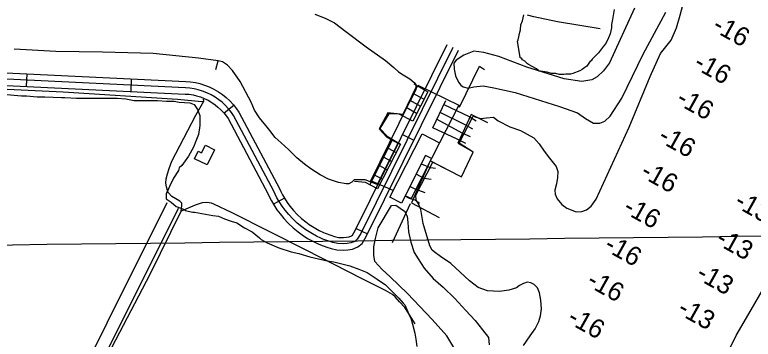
# Model space of a CAD drawing. Extents: x 3683402 to 3721514, y 487807 to 513565.
# Drawn here: x 3701138 to 3702904, y 505272 to 506048 of the extents above; entities that cross this region are included whole.
import ezdxf

# ---------------------------------------------------------------- set-up
doc = ezdxf.new("R2010")
doc.units = 0
for name, color, linetype in [('V-BLDG-OTLN', 7, 'Continuous'), ('V-GRID-MAJR', 7, 'Continuous'), ('V-LEVE-TOET', 7, 'Continuous'), ('V-ROAD-CNTR', 7, 'Continuous'), ('V-RRAP-FSHR', 7, 'Continuous'), ('V-RTRN-LOCK-CHMB', 7, 'Continuous'), ('V-SITE-VEGE', 7, 'Continuous'), ('V-TOPO-SHOR', 7, 'Continuous'), ('V-TOPO-SPOT', 7, 'Continuous'), ('V-UTIL-LINE', 7, 'Continuous')]:
    doc.layers.add(name, color=color, linetype=linetype)

msp = doc.modelspace()

# ---------------------------------------------------------------- linework, layer by layer
at = {"layer": 'V-BLDG-OTLN'}
for points in [[(3702034.7, 505611.3), (3702111.8, 505763), (3702153.7, 505741.7), (3702134.3, 505703.6), (3702120, 505710.9), (3702062.3, 505597.3)], [(3701615.6, 505724.6), (3701598.1, 505688.5), (3701567.7, 505703.3), (3701576.5, 505721.5), (3701584.6, 505717.5), (3701593.4, 505735.5)]]:
    msp.add_lwpolyline(points, close=True, dxfattribs=at)
at = {"layer": 'V-GRID-MAJR'}
msp.add_spline([(3687515.9, 505342.9), (3692797.3, 505402.5), (3698078.7, 505462.8), (3703360, 505523.8), (3708641.3, 505585.7), (3713922.7, 505648.3), (3719204, 505711.6)], degree=3, dxfattribs=at)
at = {"layer": 'V-LEVE-TOET'}
for points in [[(3702619.9, 506063.6), (3702559.8, 505932.3), (3702545.4, 505913.3), (3702530.1, 505899.4), (3702517.7, 505892.4), (3702493.9, 505888.3), (3702451.6, 505894.6), (3702362.1, 505922.6), (3702295, 505948.2), (3702259.7, 505957.5), (3702235.8, 505960.9), (3702211.5, 505950.9), (3702193.2, 505938.9), (3702187.7, 505931.5), (3702188.8, 505917.6), (3702191.3, 505901.7), (3702198.8, 505886.3), (3702204.3, 505879.4), (3702209.8, 505875.4), (3702221.7, 505872.5), (3702235.1, 505875), (3702258, 505877.6), (3702283.3, 505873.2), (3702334.5, 505861.9), (3702440.4, 505828), (3702483.7, 505812.8), (3702502.6, 505799.4), (3702522, 505788.6), (3702536.9, 505788.6), (3702548.8, 505793.6), (3702561.7, 505805.1), (3702589.4, 505848.4), (3702640.7, 505953.4), (3702694.5, 506053.4)], [(3702187.8, 505252), (3702170.5, 505279.9), (3702135.6, 505319), (3702076.9, 505381.2), (3702035.1, 505421.3), (3702016.4, 505438.9), (3701998.6, 505457.4), (3701996.6, 505472.6), (3701996.1, 505492.8), (3702000.4, 505512.9), (3702006.7, 505538.4), (3702038.9, 505591.6), (3702048.7, 505592.1), (3702069.4, 505577.9), (3702075.8, 505566.2), (3702077.3, 505551), (3702078.9, 505528.4), (3702084.9, 505503.9), (3702092.8, 505479.4), (3702102.7, 505464.2), (3702117, 505441.7), (3702138.2, 505417.2), (3702161.8, 505396.7), (3702189.9, 505369.3), (3702216.5, 505340.4), (3702238.6, 505316.4), (3702255.9, 505294.4), (3702270.2, 505275.8), (3702272.2, 505258.6)]]:
    msp.add_lwpolyline(points, dxfattribs=at)
at = {"layer": 'V-ROAD-CNTR'}
for p, q in [((3701166.7, 505906.4), (3701165.3, 505876.4)), ((3701416.4, 505894.4), (3701415, 505864.4)), ((3701661.8, 505830.6), (3701638.2, 505812.1)), ((3702065.1, 505761), (3702092, 505747.7)), ((3701782.4, 505609.4), (3701756.4, 505594.5)), ((3701954.2, 505537), (3701981, 505523.7))]:
    msp.add_line(p, q, dxfattribs=at)
for points in [[(3700503.8, 505938.4), (3701547, 505888.1), (3701558, 505887.2), (3701569.8, 505885.3), (3701580.2, 505882.9), (3701591.7, 505879.4), (3701602.9, 505875), (3701614.1, 505869.6), (3701624.7, 505863.4), (3701634.6, 505856.6), (3701643.1, 505849.8), (3701651.7, 505841.8), (3701660.4, 505832.3), (3701668.1, 505822.5), (3701673.4, 505814.7), (3701770.4, 505632.3), (3701773.8, 505625.1), (3701777.8, 505617.5), (3701782.7, 505608.9), (3701789.4, 505598.6), (3701795.8, 505589.8), (3701803.9, 505580), (3701813, 505570.3), (3701823.1, 505560.8), (3701833.5, 505552.3), (3701841.9, 505546.2), (3701853.3, 505538.8), (3701865.8, 505531.9), (3701875.8, 505527.1), (3701880.2, 505525.2), (3701893.4, 505520.4), (3701902.1, 505517.6), (3701911.7, 505515.4), (3701923.6, 505515.1), (3701931, 505515.7), (3701937.2, 505516.5), (3701942.8, 505518.9), (3701945.3, 505520.8), (3701951.6, 505531.9), (3702171.7, 505976.1)], [(3700525.2, 505907.3), (3701545.1, 505858.1), (3701554.5, 505857.4), (3701564.1, 505855.9), (3701572.5, 505853.9), (3701581.8, 505851.1), (3701590.9, 505847.5), (3701600, 505843.1), (3701608.6, 505838.1), (3701616.7, 505832.5), (3701623.5, 505827), (3701630.4, 505820.6), (3701637.6, 505812.9), (3701643.9, 505804.8), (3701647.7, 505799.2), (3701743.6, 505618.9), (3701746.9, 505611.8), (3701751.5, 505603.1), (3701757.1, 505593.3), (3701764.7, 505581.6), (3701772.1, 505571.4), (3701781.4, 505560.2), (3701791.7, 505549.1), (3701803.3, 505538.3), (3701815.1, 505528.5), (3701824.9, 505521.4), (3701837.9, 505513), (3701852.1, 505505.2), (3701863.4, 505499.8), (3701869.1, 505497.3), (3701883.6, 505492), (3701894.2, 505488.6), (3701908, 505485.5), (3701924.3, 505485.1), (3701934.2, 505485.9), (3701945.1, 505487.4), (3701958.1, 505492.8), (3701968.3, 505500.7), (3701978.1, 505517.7), (3702198.5, 505962.8)], [(3702185.1, 505969.5), (3701964.9, 505524.8), (3701956.8, 505510.8), (3701950.5, 505505.9), (3701941.2, 505502), (3701932.6, 505500.8), (3701923.9, 505500.1), (3701909.9, 505500.5), (3701898.1, 505503.1), (3701888.5, 505506.2), (3701874.6, 505511.3), (3701869.6, 505513.4), (3701858.9, 505518.5), (3701845.6, 505525.9), (3701833.4, 505533.8), (3701824.3, 505540.4), (3701813.2, 505549.5), (3701802.3, 505559.7), (3701792.7, 505570.1), (3701784, 505580.6), (3701777, 505590.1), (3701769.9, 505601.1), (3701764.6, 505610.3), (3701760.4, 505618.4), (3701757, 505625.6), (3701660.6, 505807), (3701656, 505813.7), (3701649, 505822.6), (3701641, 505831.2), (3701633.3, 505838.4), (3701625.7, 505844.5), (3701616.7, 505850.8), (3701607, 505856.4), (3701596.9, 505861.3), (3701586.7, 505865.3), (3701576.3, 505868.4), (3701566.9, 505870.6), (3701556.3, 505872.3), (3701546, 505873.1), (3700526.3, 505922.3)], [(3701215.1, 505023.7), (3701502.1, 505598.6)], [(3701242, 505010.5), (3701529, 505585.2)]]:
    msp.add_lwpolyline(points, dxfattribs=at)
at = {"layer": 'V-RRAP-FSHR'}
msp.add_line((3702083.5, 505595.3), (3702040.2, 505502.5), dxfattribs=at)
for points in [[(3702200.8, 505826.5), (3702248.9, 505924.5), (3702260.6, 505916.9)], [(3702092.3, 505882.7), (3702125.3, 505863.6), (3702089.2, 505793.4), (3702056.9, 505809.8), (3702031.8, 505811.1), (3702010.3, 505775.7), (3702028.2, 505757.2), (3702060.2, 505738.4), (3702004.9, 505631.8), (3701976, 505646.8), (3701949.9, 505649.1)], [(3702268.8, 505789.2), (3702229.2, 505809), (3702197.2, 505740.9), (3702233.6, 505720.1)], [(3702203.3, 505661.3), (3702131, 505698.1), (3702086, 505597.7), (3702152.4, 505562.6)]]:
    msp.add_lwpolyline(points, dxfattribs=at)
at = {"layer": 'V-RTRN-LOCK-CHMB'}
msp.add_lwpolyline([(3701988.9, 505650.9), (3702101.5, 505879.5), (3702199.3, 505831.1), (3702153.5, 505741.7), (3702153.7, 505741.7), (3702134.3, 505703.6), (3702134.1, 505703.7), (3702085.2, 505608.2), (3702071, 505614.5), (3702062.3, 505597.3), (3702034.7, 505611.3), (3702042.7, 505627.1)], close=True, dxfattribs=at)
at = {"layer": 'V-SITE-VEGE'}
for points in [[(3702571.1, 506060.3), (3702567, 506036.3), (3702564.3, 506024.3), (3702564.3, 506016.3), (3702561.5, 506001.6), (3702557.5, 505992.3), (3702550.8, 505979), (3702545.4, 505972.3), (3702538.7, 505963), (3702533.4, 505956.3), (3702518.7, 505941.7), (3702516, 505937.7), (3702513.3, 505936.4), (3702505.3, 505924.4), (3702501.2, 505921.7), (3702494.6, 505916.4), (3702489.2, 505913.8), (3702471.8, 505907.2), (3702466.5, 505905.8), (3702455.8, 505905.9), (3702450.5, 505904.5), (3702439.8, 505904.6), (3702431.8, 505907.3), (3702421.1, 505907.3), (3702410.5, 505910), (3702394.5, 505912.7), (3702391.8, 505912.7), (3702389.1, 505915.4), (3702385.1, 505918.1), (3702366.5, 505928.8), (3702363.8, 505930.2), (3702357.2, 505936.9), (3702351.9, 505939.5), (3702349.2, 505943.6), (3702346.5, 505944.9), (3702346.5, 505946.2), (3702340, 505983.6), (3702341.3, 505987.6), (3702345.4, 506006.3), (3702346.7, 506011.6), (3702348.1, 506023.6), (3702352.1, 506032.9), (3702354.8, 506047.6)], [(3701109.8, 505857.4), (3701153.7, 505853.5), (3701165.6, 505853.6), (3701191.6, 505851.7), (3701209.5, 505851.7), (3701249.4, 505849.9), (3701257.4, 505849.9), (3701285.3, 505848), (3701383, 505848.3), (3701402.9, 505846.4), (3701422.9, 505842.5), (3701478.7, 505842.7), (3701500.7, 505840.7), (3701518.6, 505840.8), (3701530.6, 505838.8), (3701556.5, 505836.9), (3701562.5, 505835), (3701566.5, 505833), (3701568.5, 505831), (3701574.5, 505821), (3701580.5, 505807.1), (3701580.6, 505783.2), (3701576.7, 505761.2), (3701570.8, 505745.3), (3701564.8, 505731.3), (3701552.9, 505709.3), (3701537.1, 505687.3), (3701531.1, 505681.3), (3701529.1, 505675.3), (3701517.2, 505657.3), (3701507.3, 505637.4), (3701505.3, 505631.4), (3701499.4, 505619.4), (3701499.4, 505607.4), (3701511.4, 505599.5), (3701523.4, 505589.6), (3701543.4, 505581.7), (3701545.4, 505579.7), (3701563.4, 505575.7), (3701567.3, 505575.8), (3701611.2, 505567.9), (3701625.2, 505566), (3701639.2, 505560), (3701655.1, 505554.1), (3701669.1, 505550.2), (3701687.1, 505538.3), (3701705.1, 505528.3), (3701723.1, 505514.4), (3701727.1, 505510.5), (3701741.1, 505502.5), (3701769, 505490.7), (3701799, 505480.8), (3701816.9, 505476.9), (3701842.9, 505469), (3701884.8, 505459.2), (3701900.7, 505457.2), (3701922.7, 505451.3), (3701938.6, 505447.4), (3701960.6, 505439.5), (3701980.6, 505431.5), (3702004.6, 505415.7), (3702024.5, 505401.8), (3702056.5, 505370), (3702066.6, 505358.1), (3702070.6, 505354.1), (3702082.6, 505326.2), (3702084.6, 505322.2), (3702088.6, 505308.3), (3702094.7, 505286.4), (3702096.7, 505272.4), (3702098.8, 505254.5)]]:
    msp.add_lwpolyline(points, dxfattribs=at)
at = {"layer": 'V-TOPO-SHOR'}
msp.add_line((3701618.1, 505916.4), (3701623.9, 505937.6), dxfattribs=at)
for points in [[(3702347.1, 505771.1), (3702378.6, 505753.5), (3702391.6, 505739.4), (3702403.5, 505721.4), (3702416.5, 505704.5), (3702432.3, 505684.6), (3702436.6, 505673.2), (3702435.9, 505658.7), (3702432.8, 505643.7), (3702428.9, 505628.4), (3702429.7, 505619), (3702434.9, 505607.6), (3702445.9, 505593.9), (3702457.8, 505584.9), (3702480.2, 505576.7), (3702493.5, 505577.5), (3702504.9, 505581.5), (3702516.3, 505590.2), (3702527.6, 505607.1), (3702606.8, 505779.1), (3702657, 505900.2), (3702682, 505955.3), (3702707.4, 505987.2), (3702720.2, 506016.3), (3702728.8, 506046.6), (3702735, 506070.2)], [(3701855.5, 506049.4), (3701880, 506039.7), (3701901.9, 506028), (3701929.2, 506007.3), (3701978.1, 505970.9), (3702024.6, 505938.6), (3702044.5, 505921.2), (3702055.5, 505911.5), (3702066.1, 505904.2), (3702082.8, 505894.1), (3702092.6, 505886), (3702096.7, 505881.1), (3702097.1, 505868.5), (3702066.1, 505809.1), (3702029.9, 505813), (3702008.9, 505775.2), (3702027.6, 505755.3), (3702054.1, 505740.4), (3702004.5, 505641.5), (3701975.6, 505653.2), (3701949.6, 505653.1), (3701943.5, 505647.4), (3701936.6, 505643.7), (3701930.1, 505643.3), (3701912.2, 505646.4), (3701888.2, 505654.9), (3701868.2, 505664.6), (3701845.4, 505679.5), (3701830.8, 505690.1), (3701812.4, 505705.4), (3701792, 505725.7), (3701774.5, 505741.1), (3701760.7, 505754), (3701748, 505770.6), (3701738.2, 505782.8), (3701723.1, 505801), (3701711.3, 505819.3), (3701702.7, 505838.3), (3701676.5, 505887.8), (3701658.1, 505914.6), (3701646.7, 505926.7), (3701634.5, 505934.8), (3701623.9, 505937.6), (3701576.7, 505944), (3701468.6, 505954.6), (3701347.1, 505957.8), (3701235.8, 505959.9), (3701136.2, 505965.2)], [(3702537.9, 506014.1), (3702435.5, 506030.8), (3702379.3, 506042.8), (3702363.9, 506046.9)], [(3701018.5, 505874.7), (3701253.1, 505863), (3701526.7, 505845.9), (3701585, 505840.6), (3701589.9, 505841.3), (3701589.2, 505845.5)], [(3701370.4, 505254), (3701461.5, 505427.8), (3701535.2, 505578), (3701537.3, 505591.9), (3701537.3, 505596.8), (3701535.2, 505598.9), (3701532.4, 505602.3), (3701512.9, 505613.4), (3701505.2, 505621.7), (3701503.8, 505624.4), (3701500.3, 505636.2), (3701498.9, 505645.2), (3701499.6, 505655.6), (3701503, 505667.5), (3701507.1, 505680), (3701513.3, 505697.3), (3701570.5, 505807.9), (3701589.9, 505841.3)], [(3702354.4, 505257.3), (3702370.4, 505279.7), (3702382.5, 505297.1), (3702390.7, 505314.4), (3702394.6, 505327.8), (3702397.3, 505344.7), (3702395.7, 505365.5), (3702392.1, 505382.7), (3702387.7, 505394.5), (3702379.8, 505402.7), (3702371.9, 505406.6), (3702362.9, 505408.2), (3702353.9, 505405.4), (3702344.9, 505400.3), (3702337.4, 505394.7), (3702319, 505389.2), (3702297, 505385.9), (3702268.3, 505387.8), (3702245.9, 505395.6), (3702225, 505411.2), (3702180.5, 505453.1), (3702156.1, 505469.9), (3702140.7, 505480.5), (3702136, 505485.2), (3702130.4, 505495), (3702114.5, 505548.3), (3702110.1, 505572.3), (3702108.9, 505581.7), (3702102.6, 505597), (3702097.9, 505604.5), (3702097, 505616.6), (3702137.6, 505695.3), (3702205.7, 505660.2), (3702233.8, 505719.2), (3702200.7, 505740.7), (3702233.9, 505804.9), (3702251.2, 505799.4), (3702266.1, 505801.5), (3702282.2, 505802.7), (3702293.6, 505794.1), (3702321.9, 505780), (3702347.1, 505771.1)], [(3702095, 505308.5), (3702079.6, 505334.2), (3702070.5, 505348), (3702058, 505361.2), (3702047.5, 505372.9), (3702041.3, 505378.5), (3702024.6, 505388.1), (3701968.3, 505416.4), (3701834.7, 505484.7), (3701657.4, 505574.3), (3701613.6, 505595), (3701608.1, 505597), (3701596.9, 505598.4), (3701585.8, 505597.6), (3701569.2, 505592.7), (3701535.2, 505578)], [(3702833.9, 505222.9), (3702862.7, 505281.2), (3702898.7, 505342.6), (3702958, 505444.1)]]:
    msp.add_lwpolyline(points, dxfattribs=at)
at = {"layer": 'V-UTIL-LINE'}
for p, q in [((3702099.3, 505878.7), (3702064.2, 505806.1)), ((3702116.1, 505845.7), (3702089.8, 505859)), ((3702082.4, 505843.6), (3702107.6, 505829.2)), ((3702098.6, 505811.7), (3702073.7, 505825.7)), ((3702040.7, 505749.9), (3701986.8, 505641.2)), ((3702030.3, 505728.9), (3702049.8, 505718.4)), ((3702038.7, 505697), (3702019.6, 505707.3)), ((3702009.6, 505687.3), (3702028.2, 505676.7)), ((3702109.9, 505691), (3702132.3, 505681.7)), ((3702143.6, 505680.3), (3702132.3, 505681.7)), ((3702016.7, 505654.5), (3701998.3, 505664.4))]:
    msp.add_line(p, q, dxfattribs=at)
for points in [[(3702216.5, 505740.2), (3702195.9, 505750.5), (3702137.4, 505777.4), (3702168.5, 505842.4)], [(3702163.8, 505832.7), (3702224, 505804), (3702240.9, 505793.8)], [(3702233.4, 505773.8), (3702213.1, 505785.4), (3702154.8, 505813.8)], [(3702147.3, 505798.1), (3702206.8, 505765.7), (3702226.8, 505756.8)], [(3702133.1, 505653.9), (3702116.9, 505656.2), (3702097.5, 505666.6)], [(3702118.7, 505621.6), (3702095.4, 505630.4), (3702082.4, 505636.9)], [(3702105.8, 505596.4), (3702094.8, 505604.7), (3702081.7, 505608), (3702070.9, 505614.1)]]:
    msp.add_lwpolyline(points, dxfattribs=at)

# ---------------------------------------------------------------- texts
at = {"layer": 'V-TOPO-SPOT'}
for s, p in [('-16', (3702802.8, 506011.4)), ('-16', (3702758.3, 505921.8)), ('-16', (3702716.7, 505836.6)), ('-16', (3702673.4, 505746.7)), ('-16', (3702631.1, 505662.1)), ('-13', (3702855.5, 505590.9)), ('-16', (3702589.6, 505576.6)), ('-13', (3702810.9, 505501.7)), ('-16', (3702544.3, 505486.6)), ('-13', (3702764.2, 505418.3)), ('-16', (3702502.4, 505401.5)), ('-13', (3702719.6, 505334.8)), ('-16', (3702456.2, 505313))]:
    msp.add_text(s, height=45, rotation=330.7933, dxfattribs=at).set_placement(p)

doc.saveas('drawing.dxf')
